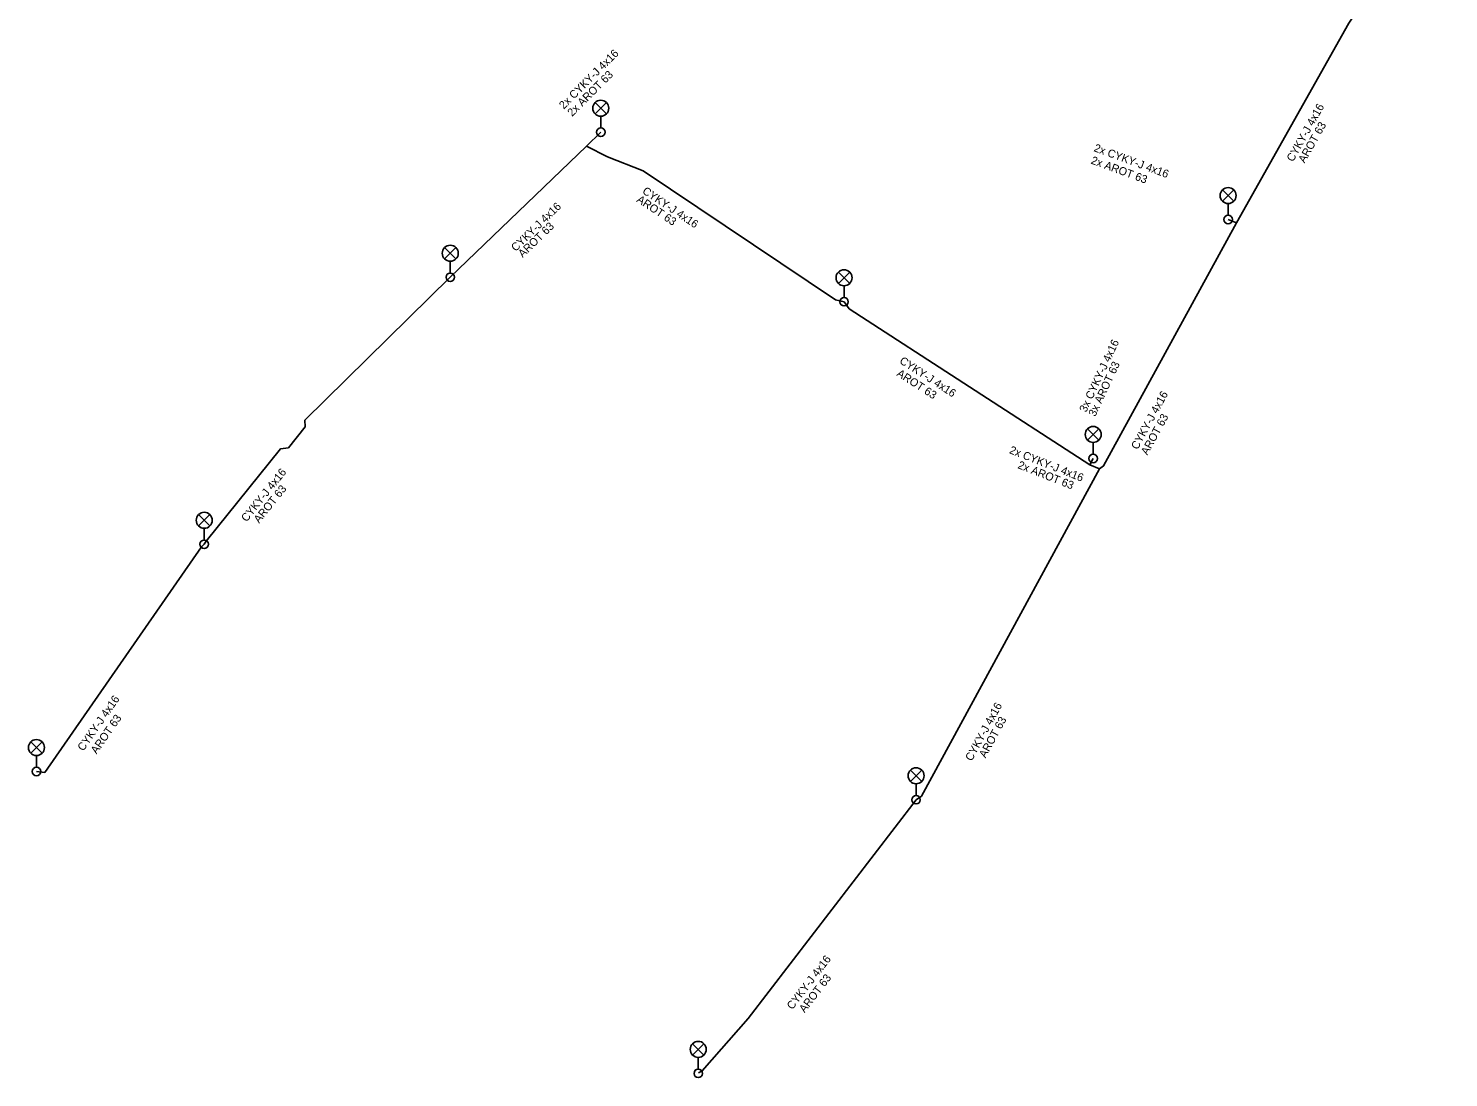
# Model space of a CAD drawing. Extents: x -600499 to -600324, y -1203856 to -1203661.
# Drawn here: x -600498.5 to -600365.4, y -1203855.9 to -1203757.5 of the extents above; entities that cross this region are included whole.
import ezdxf

# ---------------------------------------------------------------- set-up
doc = ezdxf.new("R2010")
doc.units = 0
for name, color, linetype in [('CIZÍ_PODZEM', 7, 'Continuous'), ('Default', 7, 'Continuous'), ('Vrstva 13', 7, 'Continuous'), ('Vrstva 5', 7, 'Continuous'), ('Vrstva 6', 7, 'Continuous'), ('ZP_EON', 7, 'Continuous')]:
    doc.layers.add(name, color=color, linetype=linetype)

# ---------------------------------------------------------------- blocks, each defined once
blk = doc.blocks.new('6.560')
at = {"layer": 'ZP_EON'}
for p, q in [((-0.53, 1.72), (0.53, 2.78)), ((-0.53, 2.78), (0.53, 1.72)), ((0, 1.5), (0, 0.4))]:
    blk.add_line(p, q, dxfattribs=at)
for centre, radius in [((0, 2.25), 0.75), ((0, 0), 0.4)]:
    blk.add_circle(centre, radius, dxfattribs=at)

msp = doc.modelspace()

# ---------------------------------------------------------------- linework, layer by layer
at = {"layer": 'Vrstva 13'}
for p, q in [((-600446.22, -1203768.53), (-600444.9, -1203767.21)), ((-600446.22, -1203768.53), (-600459, -1203780.81)), ((-600385.32, -1203775.71), (-600386.1, -1203775.4)), ((-600399.06, -1203798.4), (-600398.75, -1203797.8)), ((-600398.15, -1203798.76), (-600399.06, -1203798.4))]:
    msp.add_line(p, q, dxfattribs=at)
for points in [[(-600365.44, -1203743.11), (-600370.1, -1203749.97), (-600374.79, -1203756.99), (-600385.32, -1203775.71)], [(-600422.1, -1203783.1), (-600422.9, -1203782.92), (-600440.93, -1203770.82), (-600444.27, -1203769.52), (-600446.22, -1203768.53)], [(-600385.32, -1203775.71), (-600397.78, -1203798.5), (-600398.15, -1203798.76)], [(-600459, -1203780.81), (-600472.62, -1203794.22), (-600472.61, -1203794.82), (-600474.17, -1203796.79), (-600474.92, -1203796.91), (-600481.89, -1203805.57), (-600482.06, -1203805.85)], [(-600399.06, -1203798.4), (-600421.61, -1203783.78), (-600422.1, -1203783.1)], [(-600398.15, -1203798.76), (-600414.84, -1203829.48), (-600415.35, -1203829.8)], [(-600482.06, -1203805.85), (-600482.32, -1203806.09), (-600497.01, -1203827.25), (-600497.79, -1203827.16)], [(-600415.35, -1203829.8), (-600431.08, -1203850.33), (-600435.4, -1203855.23), (-600435.73, -1203855.41)]]:
    msp.add_lwpolyline(points, dxfattribs=at)
at = {"layer": 'Vrstva 5'}
for p, q in [((-600446.22, -1203768.53), (-600444.9, -1203767.21)), ((-600446.22, -1203768.53), (-600459, -1203780.81)), ((-600385.32, -1203775.71), (-600386.1, -1203775.4)), ((-600399.06, -1203798.4), (-600398.75, -1203797.8)), ((-600398.15, -1203798.76), (-600399.06, -1203798.4))]:
    msp.add_line(p, q, dxfattribs=at)
for points in [[(-600365.44, -1203743.11), (-600370.1, -1203749.97), (-600374.79, -1203756.99), (-600385.32, -1203775.71)], [(-600422.1, -1203783.1), (-600422.9, -1203782.92), (-600440.93, -1203770.82), (-600444.27, -1203769.52), (-600446.22, -1203768.53)], [(-600385.32, -1203775.71), (-600397.78, -1203798.5), (-600398.15, -1203798.76)], [(-600459, -1203780.81), (-600472.62, -1203794.22), (-600472.61, -1203794.82), (-600474.17, -1203796.79), (-600474.92, -1203796.91), (-600481.89, -1203805.57), (-600482.06, -1203805.85)], [(-600399.06, -1203798.4), (-600421.61, -1203783.78), (-600422.1, -1203783.1)], [(-600398.15, -1203798.76), (-600414.84, -1203829.48), (-600415.35, -1203829.8)], [(-600482.06, -1203805.85), (-600482.32, -1203806.09), (-600497.01, -1203827.25), (-600497.79, -1203827.16)], [(-600415.35, -1203829.8), (-600431.08, -1203850.33), (-600435.4, -1203855.23), (-600435.73, -1203855.41)]]:
    msp.add_lwpolyline(points, dxfattribs=at)

# ---------------------------------------------------------------- block references
at = {"layer": 'Default'}
for p in [(-600444.9, -1203767.21), (-600386.1, -1203775.4), (-600459, -1203780.81), (-600422.1, -1203783.1), (-600398.75, -1203797.8), (-600482.06, -1203805.85), (-600497.79, -1203827.16), (-600415.35, -1203829.8), (-600435.76, -1203855.46)]:
    msp.add_blockref('6.560', p, dxfattribs=at)

# ---------------------------------------------------------------- texts
at = {"layer": 'CIZÍ_PODZEM'}
for s, rotation, p in [('2x AROT 63', 45, (-600447.58, -1203765.78)), ('AROT 63', 60.6422, (-600378.93, -1203770.15)), ('2x AROT 63', 339.7435, (-600399.02, -1203770.13)), ('AROT 63', 326.146, (-600441.6, -1203773.68)), ('AROT 63', 44.1143, (-600452.21, -1203779.01)), ('AROT 63', 327.0432, (-600417.23, -1203790)), ('3x AROT 63', 64.9831, (-600398.56, -1203793.93)), ('AROT 63', 61.3332, (-600393.67, -1203797.54)), ('2x AROT 63', 338.416, (-600405.88, -1203798.69)), ('AROT 63', 51.1712, (-600476.92, -1203803.92)), ('AROT 63', 55.2303, (-600492.15, -1203825.57)), ('AROT 63', 61.485, (-600408.84, -1203825.94)), ('AROT 63', 52.5554, (-600425.79, -1203849.83))]:
    msp.add_text(s, height=0.75, rotation=rotation, dxfattribs=at).set_placement(p)
at = {"layer": 'Vrstva 6'}
for s, rotation, p in [('2x CYKY-J 4x16', 45, (-600448.36, -1203765.09)), ('CYKY-J 4x16', 60.6422, (-600380.02, -1203770.04)), ('2x CYKY-J 4x16', 339.7435, (-600398.74, -1203768.97)), ('CYKY-J 4x16', 326.146, (-600441.07, -1203772.89)), ('CYKY-J 4x16', 44.1143, (-600452.87, -1203778.44)), ('3x CYKY-J 4x16', 64.9831, (-600399.41, -1203793.53)), ('CYKY-J 4x16', 327.0432, (-600416.97, -1203788.82)), ('CYKY-J 4x16', 61.3332, (-600394.59, -1203797.03)), ('2x CYKY-J 4x16', 338.416, (-600406.67, -1203797.29)), ('CYKY-J 4x16', 51.1712, (-600478.09, -1203803.8)), ('CYKY-J 4x16', 55.2303, (-600493.39, -1203825.3)), ('CYKY-J 4x16', 61.485, (-600410.13, -1203826.24)), ('CYKY-J 4x16', 52.5554, (-600426.94, -1203849.54))]:
    msp.add_text(s, height=0.75, rotation=rotation, dxfattribs=at).set_placement(p)

doc.saveas('drawing.dxf')
